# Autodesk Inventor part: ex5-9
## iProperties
Shininess: 64.0
Length Units: 11272
Angle Units: 11279
Time Units: 11290
Mass Units: 11286
Length Display Precision: 3
Angle Display Precision: 2
Compacted: True
Part Number: ex5-9
Document SubType Name: Modeling
Created: 2002-09
Designer: Elise Moss
Density: 0.0
Volumn: 0.0
Area: 0.0
PropertySet Name: Model Information
Control State: 0
Master: False
Checked Out: False
Author: Elise Moss
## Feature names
1. Revolution1
2. Shell1
3. Hole1
4. Loft1
5. Sweep1
6. Coil1
